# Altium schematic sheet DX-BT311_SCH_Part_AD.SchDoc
size A4
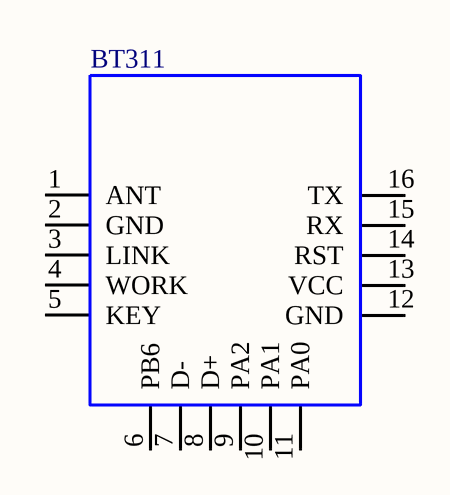
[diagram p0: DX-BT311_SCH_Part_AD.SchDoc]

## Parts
BT311  BT311  [封装]  (value not drawn)

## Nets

Not connected (* = marked no-connect by the designer): BT311 1(ANT) 2(GND) 3(LINK) 4(WORK) 5(KEY) 6(PB6) 7(D-) 8(D+) 9(PA2) 10(PA1) 11(PA0) 12(GND) 13(VCC) 14(RST) 15(RX) 16(TX)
